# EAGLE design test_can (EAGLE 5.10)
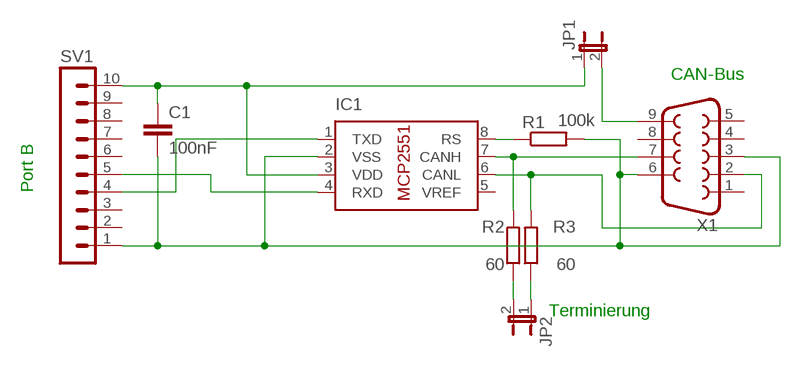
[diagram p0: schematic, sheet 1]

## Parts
C1  100nF  C-EU050-025X075  [C050-025X075]
IC1  MCP2551/SN  [SO08]
JP1  JP1E  [JP1]
JP2  JP1E  [JP1]
R1  100k  R-EU_0207/10  [0207/10]
R2  60  R-EU_0207/10  [0207/10]
R3  60  R-EU_0207/10  [0207/10]
SV1  MA10-1W  [MA10-1W]
X1  F09HP  [F09HP]

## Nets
N$1: JP1.2 X1.9
N$2: JP2.2 R2.1
N$3: IC1.7(CANH) R2.2 X1.7
N$4: JP2.1 R3.1
N$5: IC1.6(CANL) R3.2 X1.2
N$6: IC1.8(RS) R1.1
N$7: IC1.1(TXD) SV1.4
N$8: IC1.4(RXD) SV1.5
VDD: C1.1 IC1.3(VDD) JP1.1 SV1.10
VSS: C1.2 IC1.2(VSS) R1.2 SV1.1 X1.3 X1.6
Unconnected: IC1.5(VREF) SV1.2 SV1.3 SV1.6 SV1.7 SV1.8 SV1.9 X1.1 X1.4 X1.5 X1.8

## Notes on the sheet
- CAN-Bus
- Port B
- Terminierung

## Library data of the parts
C1 = rcl:C-EU: CAPACITOR, European symbol
IC1 = microchip-dspic:MCP2551: High-Speed CAN Transceiver
JP1 JP2 = jumper:JP1E: JUMPER
R1-R3 = rcl:R-EU_: RESISTOR, European symbol
SV1 = con-lstb:MA10-1W: PIN HEADER
X1 = con-subd:F09: SUB-D

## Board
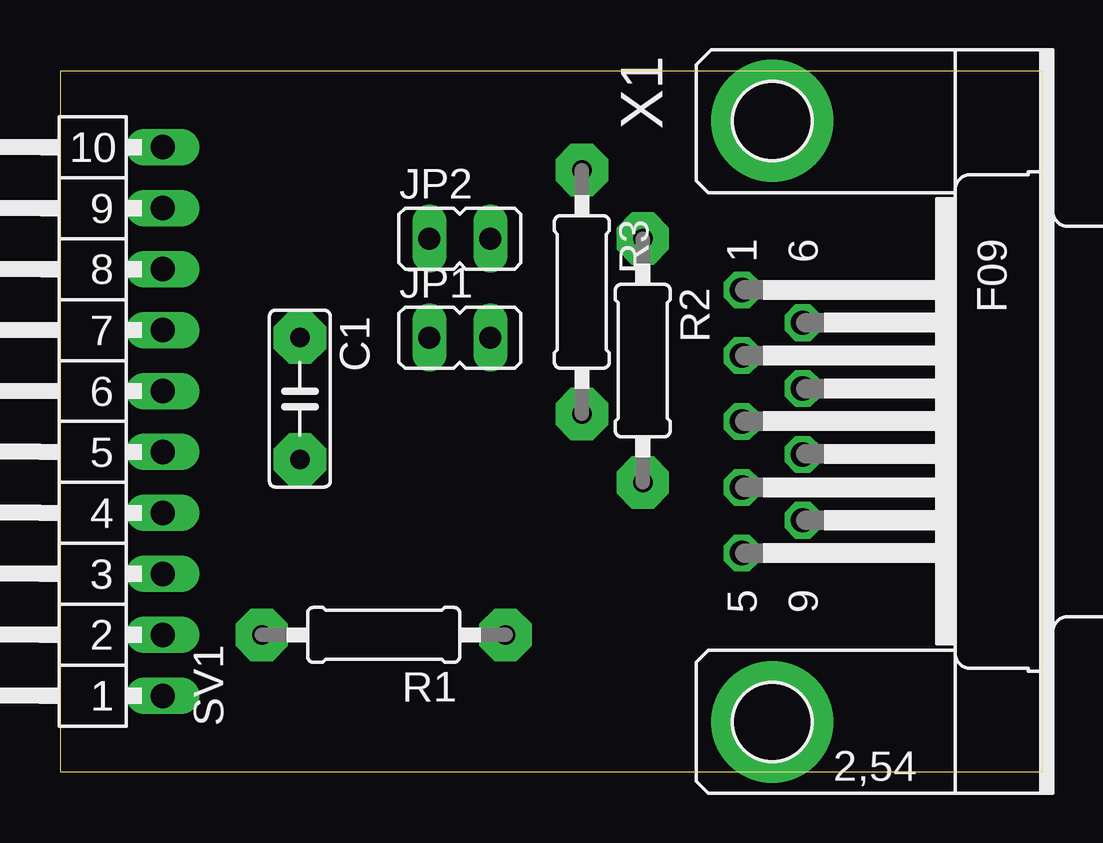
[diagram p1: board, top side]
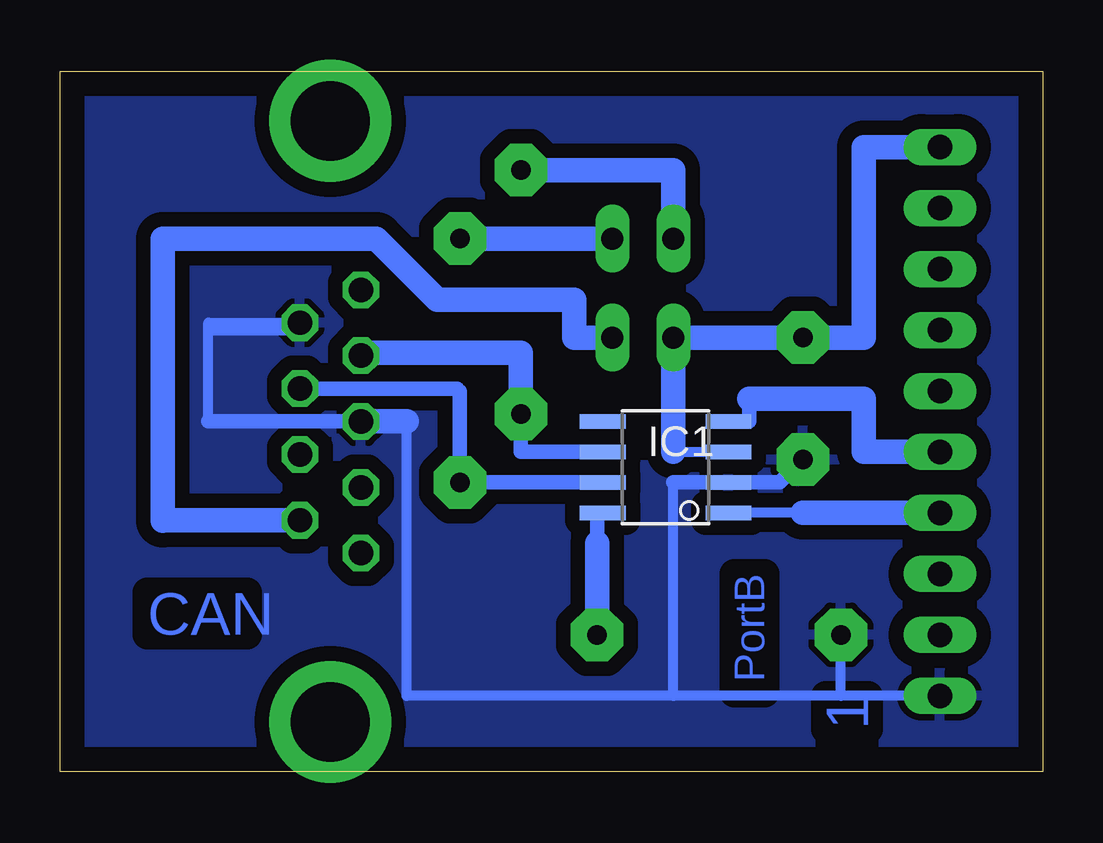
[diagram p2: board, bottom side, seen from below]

Size 40.95 x 29.2 mm. Coordinates in mm from the lower left corner, seen from the top.
Outline: 0,0 40.95,0 40.95,29.2 0,29.2 0,0
Copper layers (1*16): Top 0.035mm / dielectric 1.5mm / Bottom 0.035mm
Design rules "default": minimum track width 10mil, minimum drill 24mil, track to track 8mil, track to pad 8mil, pad to pad 8mil, via to via 8mil, smd to smd 8mil, copper to edge 40mil, drill to drill 8mil, minimum pad ring 10mil, minimum via ring 8mil, stop-mask expansion 4mil, vias tented up to drill 0mil, thermal gap 10mil

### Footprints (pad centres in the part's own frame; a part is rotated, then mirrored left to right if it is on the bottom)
C050-025X075 = drill 0.813 pad 2.184 octagon: 1 -2.54,0; 2 2.54,0
SO08 = smd 0.61 x 1.905: 1 -1.905,-2.616; 2 -0.635,-2.616; 3 0.635,-2.616; 4 1.905,-2.616; 5 1.905,2.616; 6 0.635,2.616; 7 -0.635,2.616; 8 -1.905,2.616
JP1 = drill 0.914 long: 1 0,-1.27; 2 0,1.27
0207/10 = drill 0.813 pad 2.184 octagon: 1 -5.08,0; 2 5.08,0
MA10-1W = drill 1.016 long: 1 -11.43,0; 2 -8.89,0; 3 -6.35,0; 4 -3.81,0; 5 -1.27,0; 6 1.27,0; 7 3.81,0; 8 6.35,0; 9 8.89,0; 10 11.43,0
F09HP = drill 1.016 octagon: 1 -5.486,-1.27; 2 -2.743,-1.27; 3 0,-1.27; 4 2.743,-1.27; 5 5.486,-1.27; 6 -4.115,1.27; 7 -1.372,1.27; 8 1.372,1.27; 9 4.115,1.27 | drill 3.302 pad 5.08 round: G1 -12.522,0; G2 12.522,0

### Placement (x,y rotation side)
C1  10,15.55 270 top
IC1  15.71,12.7 90 bottom
JP1  16.66,18.09 270 top
JP2  16.66,22.22 270 top
R1  13.49,5.71 180 top
R2  24.28,17.14 270 top
R3  21.74,20 270 top
SV1  4.28,14.6 90 top
X1  29.68,14.6 270 top

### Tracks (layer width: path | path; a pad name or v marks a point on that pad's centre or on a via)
N$1
  Bottom 1.016: X1.9 36.36,10.49 36.66,10.47 36.66,22.22 27.77,22.22 25.23,19.68 19.52,19.68 19.52,18.09 JP1.2
N$2
  Bottom 1.016: JP2.2 R2.1
N$3
  Bottom 0.406: 24.28,15.87 24.38,15.97
  Bottom 0.61: IC1.7 R2.2 24.28,15.87 | 24.38,15.97 X1.7
N$4
  Bottom 1.016: R3.1 15.39,25.08 JP2.1
N$5
  Bottom 0.406: 28.3,17.46 X1.2
  Bottom 0.61: R3.2 21.74,13.33 IC1.6
  Bottom 1.016: R3.2 21.74,17.46 28.3,17.46
N$6
  Bottom 0.406: 18.57,10.79 IC1.8
  Bottom 0.61: 18.57,9.52 18.57,10.79
  Bottom 1.016: R1.1 18.57,9.52
N$7
  Bottom 0.406: 9.68,10.79 IC1.1
  Bottom 1.016: SV1.4 9.68,10.79 10,10.79
N$8
  Bottom 0.61: 12.22,15.55 12.22,14.6 IC1.4
  Bottom 1.016: SV1.5 7.46,13.33 7.46,15.55 12.22,15.55
VDD
  Bottom 0.406: 15.39,13.33 IC1.3
  Bottom 1.016: SV1.10 7.46,26.03 7.46,18.09 C1.1 JP1.1 15.39,13.33
VSS
  Bottom 0.406: 34.76,14.6 34.76,18.41 | 34.76,18.41 30.95,18.41 X1.6 34.76,18.71 34.76,18.41 | SV1.1 8.41,3.17 | 8.41,3.17 15.39,3.17 | 15.39,3.17 15.39,12.06 | 26.5,14.6 26.5,3.17 15.39,3.17 | 8.41,3.17 R1.2
  Bottom 0.61: X1.3 34.76,14.6 | 15.39,12.06 IC1.2 10.95,12.06 C1.2
  Bottom 1.016: 26.5,14.6 X1.3
  pour Bottom (isolate 0.61): -0.8,29.84 46.19,29.84 46.19,-0.64 -0.8,-0.64

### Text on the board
Bottom: PortB | CAN | 1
